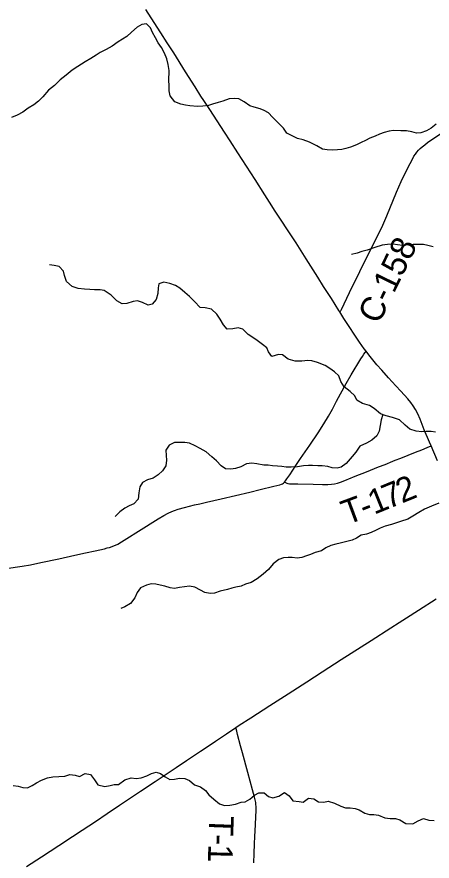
# Model space of a CAD drawing. Extents: x 0 to 1101, y 0 to 440.
# Drawn here: x 479.8 to 508.7, y 275.1 to 333.9 of the extents above; entities that cross this region are included whole.
import ezdxf

# ---------------------------------------------------------------- set-up
doc = ezdxf.new("R2010")
doc.units = 0
for name, color, linetype in [('GM_X_County_Road', 7, 'Continuous'), ('GM_X_County_Road_Text', 7, 'Continuous'), ('GM_X_Minor_River', 7, 'Continuous'), ('GM_X_State_Route', 7, 'Continuous'), ('GM_X_Township_Road', 7, 'Continuous'), ('GM_X_Township_Road_Text', 7, 'Continuous')]:
    doc.layers.add(name, color=color, linetype=linetype)

msp = doc.modelspace()

# ---------------------------------------------------------------- linework, layer by layer
at = {"layer": 'GM_X_County_Road'}
for points in [[(502.28, 313.374), (502.308, 313.403), (502.33, 313.426), (502.355, 313.455), (502.381, 313.494), (502.406, 313.539), (502.959, 314.716), (503.677, 316.188), (504.259, 317.356), (505.197, 319.243), (505.564, 320.06), (506.238, 321.718), (506.556, 322.452), (506.989, 323.36), (507.361, 324.067), (507.437, 324.213), (507.548, 324.365), (507.649, 324.5), (507.762, 324.638), (507.871, 324.756), (508.021, 324.88), (508.201, 325.018), (508.388, 325.162), (510.456, 326.564)], [(480.456, 274.716), (481.504, 275.399), (482.706, 276.175), (483.669, 276.807), (484.341, 277.245), (485.263, 277.853), (486.086, 278.4), (486.936, 278.982), (488.406, 279.968), (489.415, 280.641), (490.872, 281.612), (491.607, 282.097), (492.576, 282.751), (492.902, 282.969), (493.628, 283.457), (494.385, 283.968), (495.046, 284.407), (495.27, 284.556), (496.081, 285.086), (497.401, 285.927), (498.687, 286.754), (499.991, 287.586), (501.057, 288.273), (502.386, 289.134), (504.456, 290.463), (505.838, 291.348), (506.418, 291.72), (506.919, 292.044), (507.75, 292.578), (508.998, 293.364)]]:
    msp.add_lwpolyline(points, dxfattribs=at)
at = {"layer": 'GM_X_Minor_River'}
for points in [[(495.614, 327.995), (495.241, 328.206), (494.922, 328.245), (494.569, 328.216), (494.144, 328.052), (493.812, 327.955), (493.423, 327.847), (493.125, 327.749), (492.747, 327.698), (492.36, 327.682), (491.824, 327.724), (491.529, 327.774), (491.211, 327.848), (490.78, 328.002), (490.456, 328.417), (490.404, 328.782), (490.387, 329.158), (490.381, 329.477), (490.392, 330.194), (490.33, 330.605), (490.223, 331.005), (490.069, 331.394), (489.859, 331.796), (489.636, 332.118), (489.436, 332.463), (489.237, 332.842), (489.093, 333.151), (488.824, 333.451), (488.493, 333.4), (488.159, 333.211), (487.778, 332.864), (487.442, 332.551), (487.143, 332.362), (486.832, 332.196), (486.417, 331.873), (486.014, 331.663), (485.589, 331.442), (485.301, 331.264), (484.932, 331.019), (484.553, 330.798), (484.035, 330.476), (483.631, 330.209), (483.216, 329.874), (482.811, 329.539), (482.406, 329.135), (482.002, 328.812), (481.607, 328.351), (481.294, 328.06), (480.96, 327.803), (480.58, 327.559), (480.199, 327.292), (479.808, 327.082), (479.418, 326.917)], [(508.987, 326.455), (508.651, 326.164), (508.329, 325.976), (507.917, 325.834), (507.62, 325.827), (507.302, 325.912), (506.915, 325.975), (506.539, 325.992), (506.015, 326), (505.718, 325.959), (505.363, 325.874), (505.054, 325.753), (504.732, 325.622), (504.376, 325.468), (504.077, 325.313), (503.767, 325.17), (503.434, 325.004), (503.021, 324.852), (502.7, 324.743), (502.414, 324.69), (502.117, 324.649), (501.764, 324.632), (501.41, 324.649), (501.081, 324.711), (500.685, 324.945), (500.165, 325.203), (499.734, 325.347), (499.325, 325.444), (499.02, 325.62), (498.601, 325.831), (498.356, 326.165), (497.963, 326.57), (497.593, 326.94), (497.324, 327.24), (497.019, 327.404), (496.724, 327.522), (496.304, 327.643), (496.009, 327.716), (495.614, 327.995)], [(508.773, 317.909), (508.421, 317.994), (508.102, 318.056), (507.681, 318.074), (507.396, 318.067), (506.985, 318.028), (506.653, 317.988), (506.289, 318.05), (506.005, 318.078), (505.594, 318.061), (505.24, 318.021), (504.724, 317.847), (504.197, 317.673), (503.808, 317.565), (503.487, 317.468), (503.086, 317.36)], [(493.706, 313.204), (493.335, 313.552), (492.903, 313.638), (492.561, 313.666), (492.157, 314.082), (491.81, 314.441), (491.495, 314.719), (491.146, 315.02), (490.829, 315.196), (490.433, 315.35), (490.035, 315.447), (489.669, 315.328), (489.63, 315.033), (489.612, 314.657), (489.48, 314.227), (489.213, 313.912), (488.927, 313.837), (488.531, 314.025), (488.179, 314.145), (487.893, 314.081), (487.446, 313.951), (487.127, 313.922), (486.754, 314.144), (486.349, 314.526), (485.876, 314.852), (485.591, 314.902), (485.192, 314.909), (484.862, 314.925), (484.509, 314.942), (484.065, 315.006), (483.645, 315.126), (483.252, 315.485), (483.11, 315.897), (483.035, 316.206), (482.732, 316.529), (482.391, 316.592), (482.061, 316.642)], [(508.934, 304.976), (508.65, 305.026), (508.297, 305.031), (508, 305.013), (507.602, 305.053), (507.159, 305.186), (506.844, 305.475), (506.428, 305.834), (505.94, 306.001), (505.509, 306.122), (505.124, 306.265), (504.662, 306.636), (504.357, 306.834), (503.869, 306.978), (503.463, 307.212), (503.319, 307.522), (502.993, 307.823), (502.588, 308.137), (502.343, 308.516), (502.201, 308.905), (501.92, 309.194), (501.593, 309.416), (501.254, 309.626), (500.733, 309.839), (500.336, 309.959), (500.051, 309.986), (499.64, 309.936), (499.161, 309.943), (498.685, 310.076), (498.29, 310.378), (498.006, 310.394), (497.547, 310.264), (497.313, 310.575), (497.203, 310.862), (496.899, 311.094), (496.437, 311.443), (495.907, 311.793), (495.525, 312.151), (495.207, 312.247), (494.83, 312.196), (494.442, 312.168), (494.173, 312.457), (493.951, 312.848), (493.706, 313.204)], [(505.274, 306.209), (505.151, 305.843), (505.025, 305.048), (504.849, 304.721), (504.513, 304.419), (504.134, 304.208), (503.674, 304.011), (503.406, 303.594), (503.15, 303.29), (502.732, 302.796), (502.374, 302.54), (502.088, 302.465), (501.758, 302.504), (501.452, 302.588), (501.053, 302.629), (500.757, 302.633), (500.381, 302.651), (500.096, 302.655), (499.754, 302.638), (499.331, 302.576), (498.885, 302.537), (498.544, 302.543), (498.236, 302.582), (497.952, 302.609), (497.599, 302.649), (497.291, 302.676), (496.984, 302.681), (496.506, 302.78), (496.142, 302.831), (495.788, 302.768), (495.397, 302.569), (495.007, 302.45), (494.688, 302.41), (494.312, 302.427), (494.007, 302.648), (493.693, 302.983), (493.356, 303.273), (492.974, 303.62), (492.544, 303.855), (492.216, 304.03), (491.82, 304.219), (491.49, 304.27), (491.148, 304.275), (490.76, 304.258), (490.393, 304.082), (490.159, 303.721), (490.187, 303.357), (490.205, 303.038), (490.153, 302.64), (489.92, 302.279), (489.63, 302.022), (489.285, 301.777), (488.895, 301.658), (488.527, 301.482), (488.351, 301.166), (488.277, 300.757), (488.235, 300.314), (487.934, 300), (487.612, 299.846), (487.302, 299.691), (486.967, 299.435), (486.643, 299.098)], [(509.187, 300.043), (508.671, 299.835), (508.177, 299.615), (507.786, 299.393), (507.36, 299.138), (507.015, 298.927), (506.511, 298.753), (506.155, 298.633), (505.869, 298.547), (505.445, 298.44), (505.101, 298.286), (504.814, 298.154), (504.458, 298), (504.148, 297.879), (503.76, 297.817), (503.448, 297.606), (503.138, 297.463), (502.589, 297.323), (502.302, 297.237), (501.994, 297.184), (501.661, 297.076), (501.317, 296.933), (500.995, 296.722), (500.571, 296.603), (500.249, 296.449), (499.951, 296.363), (499.642, 296.254)], [(499.642, 296.254), (499.299, 296.214), (498.969, 296.253), (498.673, 296.246), (498.353, 296.217), (498.043, 296.108), (497.628, 295.819), (497.303, 295.425), (496.932, 295.078), (496.517, 294.766), (496.114, 294.511), (495.713, 294.38), (495.403, 294.249), (495.048, 294.174), (494.762, 294.111), (494.453, 294.013), (493.938, 293.907), (493.548, 293.754), (493.251, 293.736), (492.888, 293.81), (492.582, 293.963), (492.175, 294.185), (491.8, 294.259), (491.114, 294.156), (490.771, 294.093), (490.464, 294.144), (490.101, 294.252), (489.772, 294.325), (489.465, 294.399), (489.146, 294.415), (488.814, 294.329), (488.389, 294.131), (488.167, 293.804), (488.002, 293.443), (487.711, 293.049), (487.308, 292.816), (487.021, 292.684)], [(479.534, 280.356), (479.886, 280.314), (480.214, 280.215), (480.532, 280.208), (480.854, 280.361), (481.154, 280.537), (481.499, 280.723), (481.912, 280.885), (482.289, 280.957), (482.71, 280.982), (483.121, 281.018), (483.487, 281.135), (483.85, 281.082), (484.144, 280.995), (484.547, 281.203), (484.92, 281.126), (485.185, 280.755), (485.428, 280.407), (485.903, 280.283), (486.279, 280.354), (486.565, 280.428), (486.861, 280.432), (487.301, 280.754), (487.759, 280.903), (488.099, 280.839), (488.441, 280.888), (488.831, 281.028), (489.153, 281.203), (489.497, 281.298)], [(489.497, 281.298), (489.801, 281.189), (490.115, 280.976), (490.441, 280.786), (490.771, 280.802), (491.114, 280.863), (491.477, 280.843), (491.815, 280.699), (492.15, 280.406), (492.579, 280.271), (492.915, 280.012), (493.158, 279.71), (493.515, 279.405), (493.906, 279.077), (494.245, 278.978), (494.61, 278.993), (495.021, 279.064), (495.41, 279.203), (495.695, 279.22), (496.007, 279.418), (496.331, 279.685), (496.642, 279.861), (497.017, 279.852), (497.319, 279.583), (497.624, 279.496), (498.025, 279.625), (498.417, 279.867), (498.753, 279.643), (499.007, 279.294), (499.438, 279.251), (499.733, 279.198), (500.092, 279.487), (500.477, 279.422), (500.791, 279.221), (501.166, 279.201), (501.463, 279.274), (501.915, 279.139), (502.354, 278.923), (502.682, 278.813), (503, 278.806), (503.34, 278.764), (503.634, 278.655), (504.027, 278.441), (504.343, 278.331), (504.639, 278.336), (504.967, 278.283), (505.419, 278.113), (505.782, 278.071), (506.157, 278.051), (506.462, 277.965), (506.889, 277.715), (507.366, 277.693), (507.745, 277.89), (508.102, 278.054), (508.486, 277.954), (508.861, 277.923)]]:
    msp.add_lwpolyline(points, dxfattribs=at)
at = {"layer": 'GM_X_State_Route'}
msp.add_lwpolyline([(509.077, 302.988), (508.636, 304.03), (508.531, 304.276), (508.163, 305.153), (507.871, 305.879), (507.709, 306.254), (507.561, 306.553), (507.399, 306.821), (507.226, 307.061), (507.012, 307.316), (506.526, 307.84), (506.18, 308.21), (505.662, 308.782), (505.199, 309.294), (504.87, 309.676), (504.307, 310.372), (504.118, 310.618), (503.977, 310.801), (503.653, 311.258), (503.374, 311.677), (502.895, 312.411), (502.572, 312.912), (502.28, 313.374), (502.223, 313.464), (501.694, 314.298), (501.152, 315.145), (500.754, 315.776), (499.947, 317.052), (499.236, 318.168), (498.637, 319.09), (498.198, 319.76), (497.743, 320.465), (497.553, 320.763), (497.057, 321.53), (496.374, 322.597), (495.169, 324.46), (494.634, 325.29), (494.241, 325.901), (493.225, 327.464), (492.816, 328.088), (492.612, 328.4), (492.213, 329.051), (491.541, 330.104), (490.711, 331.409), (490.259, 332.116), (489.804, 332.82), (489.343, 333.542), (488.769, 334.436)], dxfattribs=at)
at = {"layer": 'GM_X_Township_Road'}
for points in [[(498.422, 301.499), (498.499, 301.587), (498.597, 301.727), (498.794, 302.007), (499.209, 302.651), (499.55, 303.156), (500.189, 304.083), (500.764, 304.941), (501.17, 305.571), (501.497, 306.101), (501.765, 306.582), (502.058, 307.145), (502.726, 308.367), (503.079, 308.986), (503.736, 310.092), (503.85, 310.266), (503.964, 310.43), (504.053, 310.539), (504.118, 310.618)], [(498.422, 301.499), (498.494, 301.468), (498.592, 301.427), (498.67, 301.406), (498.784, 301.391), (499.006, 301.387), (499.352, 301.387), (500.414, 301.354), (501.086, 301.34), (501.455, 301.335), (501.699, 301.356), (501.911, 301.387), (502.108, 301.439), (502.387, 301.527), (502.798, 301.692), (502.92, 301.74), (503.353, 301.912), (504.15, 302.227), (504.982, 302.559), (505.431, 302.741), (505.967, 302.956), (506.14, 303.025), (506.538, 303.182), (507.559, 303.589), (507.99, 303.762), (508.368, 303.919), (508.636, 304.03)], [(479.043, 295.491), (480.167, 295.654), (480.732, 295.743), (481.458, 295.892), (482.702, 296.166), (483.828, 296.411), (484.576, 296.571), (485.243, 296.712), (485.895, 296.86), (486.076, 296.912), (486.235, 296.957), (486.532, 297.061), (486.817, 297.183), (487.076, 297.331), (487.452, 297.57), (488.255, 298.078), (489.629, 298.94), (490.029, 299.181), (490.326, 299.341), (490.582, 299.458), (490.756, 299.527), (491.023, 299.615), (491.473, 299.739), (492.161, 299.91), (492.523, 299.997), (492.994, 300.107), (494.01, 300.343), (496.025, 300.814), (496.732, 300.984), (497.689, 301.219), (498.106, 301.325), (498.208, 301.356), (498.282, 301.386), (498.349, 301.427), (498.422, 301.499)], [(496.288, 274.979), (496.31, 275.614), (496.348, 276.303), (496.373, 276.805), (496.414, 277.624), (496.443, 278.201), (496.451, 278.59), (496.452, 278.89), (496.442, 279.041), (496.425, 279.168), (496.387, 279.359), (496.339, 279.555), (496.205, 280.062), (495.879, 281.256), (495.502, 282.64), (495.368, 283.125), (495.156, 283.918), (495.103, 284.156), (495.046, 284.407)]]:
    msp.add_lwpolyline(points, dxfattribs=at)

# ---------------------------------------------------------------- texts
at = {"layer": 'GM_X_County_Road_Text'}
msp.add_text('C-158', height=1.7045, rotation=64.05113, dxfattribs=at).set_placement((504.994, 312.44))
at = {"layer": 'GM_X_Township_Road_Text'}
for s, rotation, p in [('2', 22.21404, (506.605, 300.008)), ('7', 22.13967, (505.638, 299.614)), ('1', 21.91572, (504.665, 299.223)), ('T', 20.27012, (502.776, 298.508)), ('-', 21.50641, (504.007, 298.964)), ('T', 267.86954, (493.199, 278.271)), ('-', 267.96275, (493.152, 276.994)), ('1', 268.30576, (493.127, 276.283))]:
    msp.add_text(s, height=1.705, rotation=rotation, dxfattribs=at).set_placement(p)

doc.saveas('drawing.dxf')
